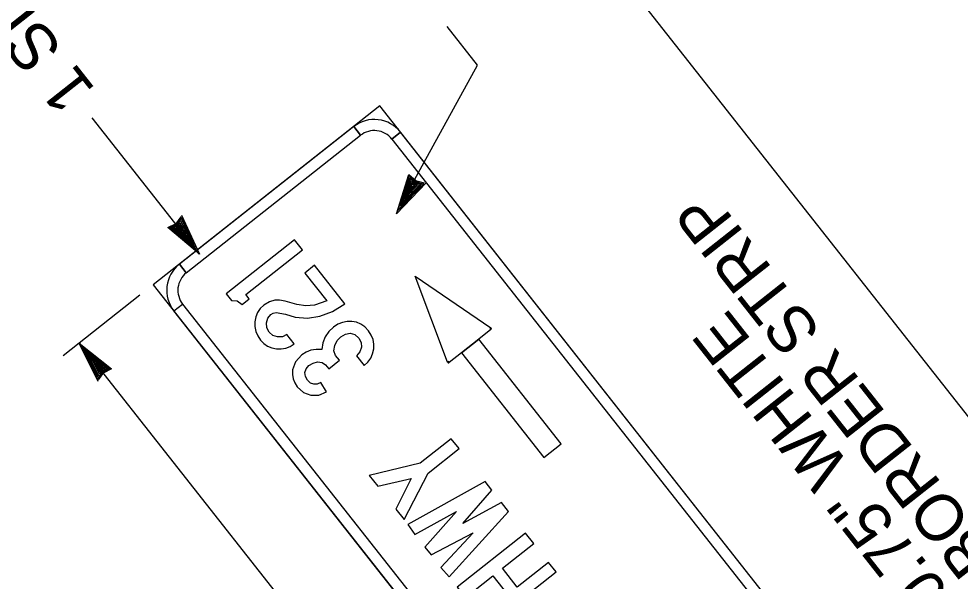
# Model space of a CAD drawing. Extents: x 672239 to 673995, y 1673540 to 1675195.
# Drawn here: x 672425.9 to 672510.8, y 1674995.2 to 1675045.8 of the extents above; entities that cross this region are included whole.
import ezdxf

# ---------------------------------------------------------------- set-up
doc = ezdxf.new("R2010")
doc.units = 0
for name, color, linetype in [('C-ALGN-SYMB', 7, 'Continuous'), ('C-ANNO-SYMB', 7, 'Continuous'), ('C-HELI-SIDE', 7, 'Continuous')]:
    doc.layers.add(name, color=color, linetype=linetype)

msp = doc.modelspace()

# ---------------------------------------------------------------- linework, layer by layer
at = {"layer": 'C-ALGN-SYMB'}
for p, q in [((672442.221, 1675024.659), (672432.563, 1675036.91)), ((672459.976, 1675028.273), (672461.093, 1675031.823)), ((672461.093, 1675031.823), (672461.732, 1675031.256)), ((672462.631, 1675031.073), (672459.976, 1675028.273)), ((672460.094, 1675028.572), (672461.129, 1675031.678)), ((672462.262, 1675030.968), (672460.122, 1675028.617)), ((672462.43, 1675030.992), (672460.239, 1675028.76)), ((672460.322, 1675028.956), (672461.187, 1675031.52)), ((672460.49, 1675029.128), (672461.323, 1675031.288)), ((672462.123, 1675030.992), (672460.49, 1675029.128)), ((672460.513, 1675029.269), (672461.236, 1675031.398)), ((672462.123, 1675030.992), (672460.513, 1675029.269)), ((672460.795, 1675029.742), (672461.323, 1675031.134)), ((672461.935, 1675030.982), (672460.795, 1675029.742)), ((672461.059, 1675030.132), (672461.336, 1675031.002)), ((672461.769, 1675030.961), (672461.059, 1675030.132)), ((672461.129, 1675031.678), (672461.651, 1675031.274)), ((672461.373, 1675031.167), (672461.174, 1675030.277)), ((672461.187, 1675031.52), (672461.41, 1675031.327)), ((672461.236, 1675031.398), (672462.123, 1675030.992)), ((672461.651, 1675030.968), (672461.266, 1675030.529)), ((672461.266, 1675030.529), (672461.392, 1675030.941)), ((672461.323, 1675031.288), (672461.935, 1675030.982)), ((672461.323, 1675031.134), (672461.769, 1675030.961)), ((672461.336, 1675031.002), (672461.651, 1675030.968)), ((672461.821, 1675031.049), (672461.373, 1675031.167)), ((672461.392, 1675030.941), (672461.492, 1675030.91)), ((672461.41, 1675031.327), (672462.123, 1675030.992)), ((672461.492, 1675030.91), (672461.821, 1675031.049)), ((672461.651, 1675031.274), (672462.447, 1675031.074)), ((672461.732, 1675031.256), (672462.069, 1675031.054)), ((672462.069, 1675031.054), (672462.43, 1675030.992)), ((672462.22, 1675031.055), (672462.262, 1675030.968)), ((672460.974, 1675030.092), (672460.763, 1675029.637)), ((672461.174, 1675030.277), (672460.974, 1675030.092)), ((672460.305, 1675028.719), (672460.897, 1675029.403)), ((672460.897, 1675029.403), (672460.322, 1675028.956)), ((672460.763, 1675029.637), (672461.094, 1675029.988)), ((672439.809, 1675027.012), (672440.521, 1675027.678)), ((672439.94, 1675027.145), (672440.521, 1675027.678)), ((672439.943, 1675027.05), (672440.459, 1675027.5)), ((672440.081, 1675027.348), (672440.568, 1675028.009)), ((672440.128, 1675027.417), (672440.443, 1675027.652)), ((672440.443, 1675027.652), (672440.638, 1675027.962)), ((672440.459, 1675027.5), (672441.174, 1675025.975)), ((672440.568, 1675028.009), (672440.5, 1675027.791)), ((672440.5, 1675027.791), (672440.596, 1675027.797)), ((672440.521, 1675027.678), (672441.504, 1675025.534)), ((672440.521, 1675027.678), (672441.626, 1675025.46)), ((672440.589, 1675028.156), (672442.221, 1675024.659)), ((672440.596, 1675027.797), (672441.959, 1675024.925)), ((672440.638, 1675027.962), (672441.87, 1675025.087)), ((672439.361, 1675027.041), (672440.128, 1675027.417)), ((672442.221, 1675024.659), (672439.361, 1675027.041)), ((672439.509, 1675027.019), (672440.081, 1675027.348)), ((672441.989, 1675024.882), (672439.509, 1675027.019)), ((672439.677, 1675027.013), (672439.94, 1675027.145)), ((672441.721, 1675025.239), (672439.677, 1675027.013)), ((672441.504, 1675025.534), (672439.809, 1675027.012)), ((672441.626, 1675025.46), (672439.943, 1675027.05)), ((672440.354, 1675027.421), (672440.075, 1675027.051)), ((672440.075, 1675027.051), (672440.822, 1675026.529)), ((672440.086, 1675026.992), (672440.416, 1675027.338)), ((672441.174, 1675025.975), (672440.086, 1675026.992)), ((672440.213, 1675026.954), (672440.364, 1675027.232)), ((672440.913, 1675026.368), (672440.213, 1675026.954)), ((672440.29, 1675026.982), (672440.357, 1675027.063)), ((672440.624, 1675026.709), (672440.29, 1675026.982)), ((672440.357, 1675027.063), (672440.354, 1675027.421)), ((672440.364, 1675027.232), (672440.624, 1675026.709)), ((672440.416, 1675027.338), (672440.913, 1675026.368)), ((672440.822, 1675026.529), (672440.918, 1675026.274)), ((672436.837, 1675020.944), (672429.932, 1675015.501)), ((672433.08, 1675013.178), (672431.377, 1675016.64)), ((672431.377, 1675016.64), (672434.285, 1675014.318)), ((672452.225, 1674990.264), (672431.41, 1675016.666)), ((672431.736, 1675016.219), (672431.612, 1675016.422)), ((672431.612, 1675016.422), (672434.137, 1675014.337)), ((672433.066, 1675013.536), (672431.644, 1675016.38)), ((672431.644, 1675016.38), (672431.674, 1675016.173)), ((672431.674, 1675016.173), (672432.098, 1675015.373)), ((672433.028, 1675013.37), (672431.736, 1675016.219)), ((672432.098, 1675015.373), (672431.888, 1675016.071)), ((672431.888, 1675016.071), (672433.968, 1675014.339)), ((672433.138, 1675013.657), (672431.988, 1675015.852)), ((672431.988, 1675015.852), (672433.703, 1675014.297)), ((672433.138, 1675013.657), (672432.111, 1675015.78)), ((672432.111, 1675015.78), (672433.837, 1675014.338)), ((672432.713, 1675015.053), (672432.365, 1675015.414)), ((672432.365, 1675015.414), (672432.573, 1675014.979)), ((672433.197, 1675013.836), (672432.451, 1675015.346)), ((672432.451, 1675015.346), (672433.559, 1675014.352)), ((672432.813, 1675014.799), (672432.713, 1675015.053)), ((672433.237, 1675013.999), (672432.72, 1675014.959)), ((672432.72, 1675014.959), (672433.432, 1675014.387)), ((672433.571, 1675014.293), (672432.813, 1675014.799)), ((672433.286, 1675014.106), (672433.015, 1675014.623)), ((672433.015, 1675014.623), (672433.355, 1675014.357)), ((672433.571, 1675013.996), (672433.098, 1675013.325)), ((672433.837, 1675014.338), (672433.138, 1675013.657)), ((672433.708, 1675014.201), (672433.138, 1675013.657)), ((672433.703, 1675014.297), (672433.197, 1675013.836)), ((672433.526, 1675013.926), (672433.216, 1675013.685)), ((672433.559, 1675014.352), (672433.237, 1675013.999)), ((672433.432, 1675014.387), (672433.286, 1675014.106)), ((672433.355, 1675014.357), (672433.29, 1675014.275)), ((672433.29, 1675014.275), (672433.3, 1675013.918)), ((672433.3, 1675013.918), (672433.571, 1675014.293)), ((672434.285, 1675014.318), (672433.526, 1675013.926)), ((672434.137, 1675014.337), (672433.571, 1675013.996)), ((672433.968, 1675014.339), (672433.708, 1675014.201)), ((672433.216, 1675013.685), (672433.028, 1675013.37)), ((672433.162, 1675013.544), (672433.066, 1675013.536))]:
    msp.add_line(p, q, dxfattribs=at)
msp.add_lwpolyline([(672461.114, 1675030.481), (672467.276, 1675041.658), (672464.53, 1675045.141)], dxfattribs=at)
at = {"layer": 'C-ANNO-SYMB'}
for p, q in [((672458.472, 1675037.99), (672438.054, 1675021.894)), ((672510.477, 1674972.024), (672458.472, 1675037.99)), ((672456.116, 1675036.133), (672440.41, 1675023.751)), ((672456.116, 1675036.133), (672456.735, 1675035.348)), ((672456.735, 1675035.348), (672456.116, 1675036.133)), ((672456.735, 1675035.348), (672456.116, 1675036.133)), ((672441.029, 1675022.966), (672456.735, 1675035.348)), ((672456.735, 1675035.348), (672456.735, 1675035.348)), ((672456.735, 1675035.348), (672456.735, 1675035.348)), ((672459.544, 1675035.015), (672460.329, 1675035.634)), ((672460.329, 1675035.634), (672459.544, 1675035.015)), ((672508.619, 1674974.38), (672460.329, 1675035.634)), ((672459.544, 1675035.015), (672507.834, 1674973.761)), ((672441.029, 1675022.966), (672440.41, 1675023.751)), ((672440.41, 1675023.751), (672441.029, 1675022.966)), ((672461.642, 1675022.662), (672461.642, 1675022.662)), ((672461.642, 1675022.662), (672461.642, 1675022.662)), ((672464.555, 1675014.936), (672461.642, 1675022.662)), ((672461.642, 1675022.662), (672468.475, 1675018.026)), ((672438.054, 1675021.894), (672490.058, 1674955.928)), ((672439.911, 1675019.538), (672440.697, 1675020.157)), ((672439.911, 1675019.538), (672440.697, 1675020.157)), ((672440.697, 1675020.157), (672440.697, 1675020.157)), ((672440.697, 1675020.157), (672440.697, 1675020.157)), ((672440.697, 1675020.157), (672488.986, 1674958.903)), ((672488.201, 1674958.284), (672439.911, 1675019.538)), ((672468.48, 1675017.866), (672467.38, 1675016.999)), ((672468.475, 1675018.026), (672468.418, 1675017.944)), ((672468.418, 1675017.944), (672468.475, 1675018.026)), ((672468.418, 1675017.944), (672468.48, 1675017.866)), ((672468.48, 1675017.866), (672468.418, 1675017.944)), ((672465.81, 1675015.761), (672467.38, 1675016.999)), ((672465.81, 1675015.761), (672467.38, 1675016.999)), ((672467.38, 1675016.999), (672465.81, 1675015.761)), ((672474.81, 1675007.575), (672467.38, 1675016.999)), ((672465.81, 1675015.761), (672464.71, 1675014.894)), ((672465.81, 1675015.761), (672473.239, 1675006.337)), ((672464.648, 1675014.973), (672464.555, 1675014.936)), ((672464.555, 1675014.936), (672464.648, 1675014.973)), ((672464.71, 1675014.894), (672464.648, 1675014.973)), ((672464.648, 1675014.973), (672464.71, 1675014.894)), ((672473.239, 1675006.337), (672474.81, 1675007.575)), ((672474.81, 1675007.575), (672474.81, 1675007.575)), ((672474.81, 1675007.575), (672474.81, 1675007.575))]:
    msp.add_line(p, q, dxfattribs=at)
for points in [[(672451.49, 1675025.041), (672450.78, 1675025.942), (672444.619, 1675021.084), (672445.088, 1675020.489), (672445.611, 1675020.447), (672446.062, 1675020.108), (672446.707, 1675020.617), (672446.389, 1675021.02)], [(672451.71, 1675022.95), (672453.689, 1675020.44), (672452.585, 1675020.062), (672451.786, 1675020.002), (672450.98, 1675020.106), (672449.931, 1675020.403), (672449.436, 1675020.503), (672449.011, 1675020.507), (672448.515, 1675020.364), (672448.016, 1675020.056), (672447.695, 1675019.749), (672447.452, 1675019.398), (672447.29, 1675019.005), (672447.208, 1675018.569), (672447.212, 1675018.122), (672447.295, 1675017.697), (672447.463, 1675017.294), (672447.71, 1675016.914), (672448.009, 1675016.601), (672448.349, 1675016.364), (672448.732, 1675016.204), (672449.154, 1675016.124), (672449.59, 1675016.118), (672449.999, 1675016.189), (672450.386, 1675016.339), (672450.745, 1675016.567), (672450.079, 1675017.412), (672449.696, 1675017.215), (672449.256, 1675017.189), (672448.836, 1675017.331), (672448.499, 1675017.627), (672448.299, 1675018.012), (672448.254, 1675018.46), (672448.367, 1675018.888), (672448.631, 1675019.21), (672448.866, 1675019.347), (672449.124, 1675019.405), (672449.953, 1675019.233), (672450.842, 1675018.976), (672451.954, 1675018.889), (672453.072, 1675019.059), (672454.196, 1675019.489), (672455.324, 1675020.177), (672452.591, 1675023.645)], [(672457.046, 1675014.608), (672457.386, 1675014.931), (672457.641, 1675015.291), (672457.819, 1675015.682), (672457.914, 1675016.109), (672457.93, 1675016.543), (672457.853, 1675016.963), (672457.689, 1675017.364), (672457.432, 1675017.752), (672457.118, 1675018.089), (672456.763, 1675018.341), (672456.376, 1675018.511), (672455.947, 1675018.596), (672455.513, 1675018.596), (672455.092, 1675018.509), (672454.686, 1675018.335), (672454.295, 1675018.079), (672453.87, 1675017.671), (672453.55, 1675017.199), (672453.34, 1675016.665), (672453.236, 1675016.075), (672452.73, 1675016.077), (672452.259, 1675015.994), (672451.827, 1675015.825), (672451.428, 1675015.568), (672450.879, 1675014.961), (672450.611, 1675014.23), (672450.59, 1675013.821), (672450.652, 1675013.432), (672450.799, 1675013.059), (672451.029, 1675012.704), (672451.582, 1675012.204), (672452.25, 1675011.956), (672452.963, 1675011.963), (672453.646, 1675012.239), (672453.14, 1675013.095), (672452.834, 1675012.946), (672452.514, 1675012.929), (672452.207, 1675013.042), (672451.94, 1675013.288), (672451.755, 1675013.631), (672451.719, 1675013.992), (672451.833, 1675014.329), (672452.084, 1675014.612), (672452.446, 1675014.829), (672452.846, 1675014.939), (672453.277, 1675014.904), (672453.582, 1675014.686), (672453.86, 1675014.333), (672454.826, 1675015.095), (672454.484, 1675015.529), (672454.324, 1675015.933), (672454.402, 1675016.432), (672454.624, 1675016.87), (672454.943, 1675017.21), (672455.365, 1675017.455), (672455.788, 1675017.524), (672456.221, 1675017.406), (672456.587, 1675017.086), (672456.785, 1675016.698), (672456.8, 1675016.265), (672456.652, 1675015.842), (672456.356, 1675015.484)], [(672458.277, 1675003.759), (672461.277, 1675004.462), (672459.91, 1675001.688), (672460.654, 1675000.745), (672462.814, 1675004.936), (672465.605, 1675007.137), (672464.904, 1675008.025), (672462.113, 1675005.825), (672457.518, 1675004.722)], [(672470.068, 1675001.475), (672469.42, 1675002.298), (672465.95, 1675000.383), (672468.544, 1675003.408), (672467.944, 1675004.169), (672460.993, 1675000.314), (672461.627, 1674999.406), (672465.369, 1675001.469), (672462.529, 1674998.262), (672463.077, 1674997.567), (672466.872, 1674999.562), (672463.974, 1674996.429), (672464.715, 1674995.593)], [(672474.343, 1674996.053), (672473.677, 1674996.898), (672470.849, 1674994.669), (672469.516, 1674996.36), (672472.343, 1674998.59), (672471.601, 1674999.531), (672465.439, 1674994.674), (672466.182, 1674993.732), (672468.653, 1674995.68), (672469.986, 1674993.988), (672467.516, 1674992.04), (672468.182, 1674991.195)]]:
    msp.add_lwpolyline(points, close=True, dxfattribs=at)
for centre, radius, start, end in [((672457.973, 1675033.777), 3, 38.2506, 128.25081), ((672457.973, 1675033.777), 2, 38.2506, 128.25081), ((672442.267, 1675021.395), 3, 128.25054, 218.25075), ((672442.267, 1675021.395), 2, 128.25054, 218.25075), ((672468.418, 1675017.944), 0.1, 308.25039, 55.35339), ((672464.648, 1675014.973), 0.1, 201.14796, 308.25039)]:
    msp.add_arc(centre, radius, start, end, dxfattribs=at)
at = {"layer": 'C-HELI-SIDE'}
msp.add_lwpolyline([(672667.197, 1675019.186), (672536.155, 1675185.409), (672435.659, 1675106.183), (672566.701, 1674939.96)], close=True, dxfattribs=at)

# ---------------------------------------------------------------- texts
at = {"layer": 'C-ALGN-SYMB'}
for s, p in [('1 SIGN REQUIRED', (672432.919, 1675039.449)), ('BORDER STRIP', (672514.191, 1674997.584)), ('0.75" WHITE ', (672509.897, 1674994.199))]:
    msp.add_text(s, height=4.2, rotation=128.25054, dxfattribs=at).set_placement(p)

doc.saveas('drawing.dxf')
